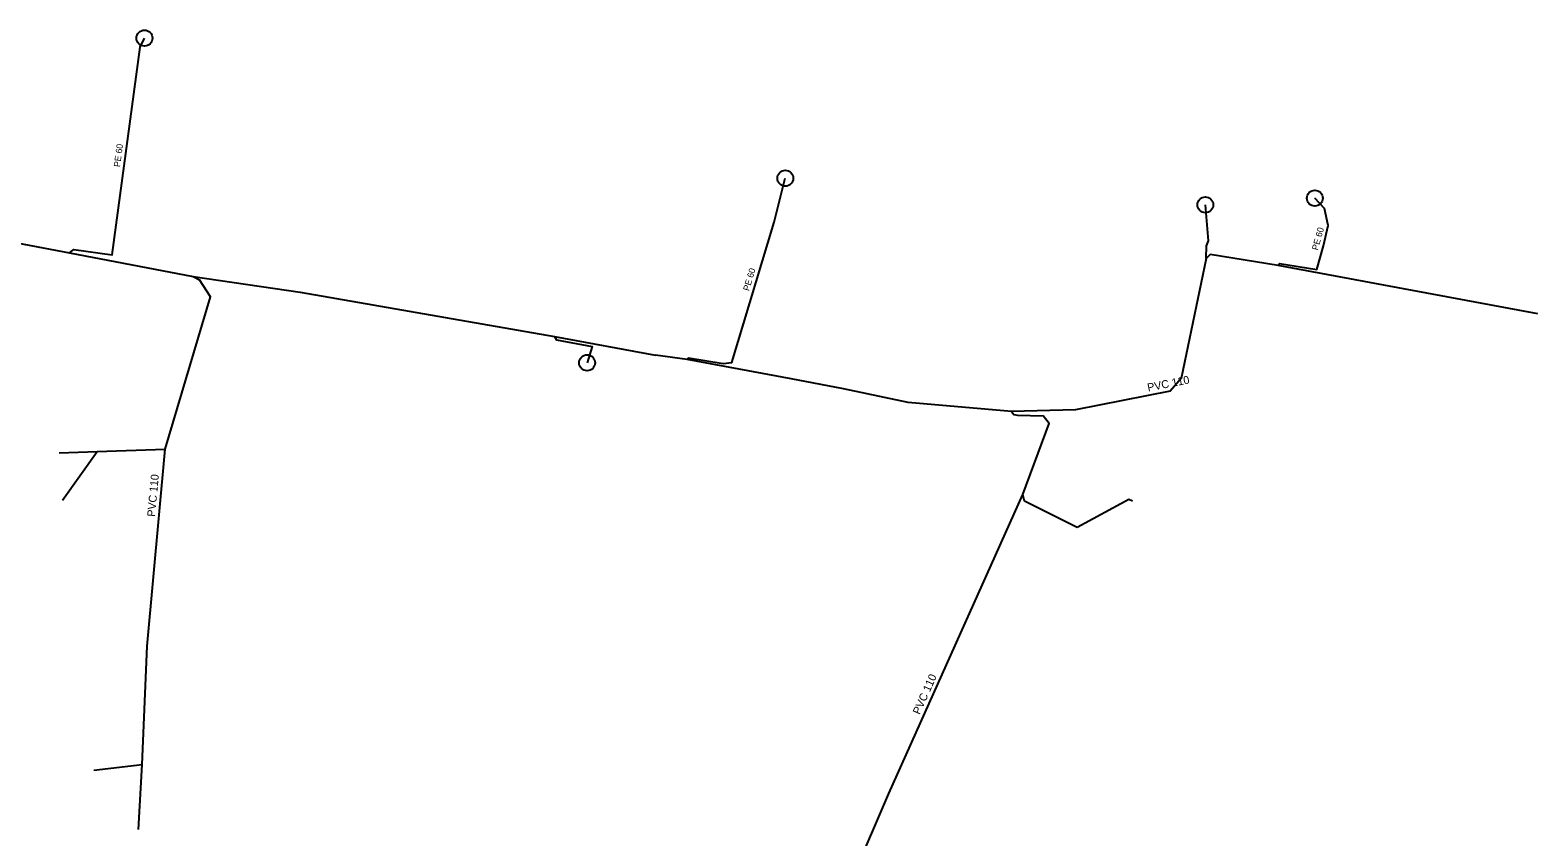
# Model space of a CAD drawing. Extents: x -687195 to -686827, y -1053873 to -1053627.
# Drawn here: x -686921.9 to -686827.2, y -1053773 to -1053722.3 of the extents above; entities that cross this region are included whole.
import ezdxf

# ---------------------------------------------------------------- set-up
doc = ezdxf.new("R2010")
doc.units = 0
for name, color, linetype in [('Kanalizační přípojky', 7, 'Continuous'), ('Kanalizační stoka', 7, 'Continuous'), ('Kanalizační šachty', 7, 'Continuous'), ('Popis', 7, 'Continuous')]:
    doc.layers.add(name, color=color, linetype=linetype)

msp = doc.modelspace()

# ---------------------------------------------------------------- linework, layer by layer
at = {"layer": 'Kanalizační přípojky'}
for points in [[(-686919.46, -1053736.25), (-686919.2, -1053736.04), (-686916.79, -1053736.37), (-686915.02, -1053723.32), (-686914.76, -1053722.75)], [(-686880.65, -1053742.95), (-686880.56, -1053742.85), (-686878.39, -1053743.2), (-686877.84, -1053743.14), (-686875.19, -1053734.31), (-686874.48, -1053731.56)], [(-686848.03, -1053736.6), (-686848.01, -1053735.8), (-686847.89, -1053735.5), (-686848.08, -1053733.23)], [(-686843.5, -1053737.05), (-686843.42, -1053736.92), (-686841.07, -1053737.29), (-686840.66, -1053735.8), (-686840.37, -1053734.52), (-686840.6, -1053733.46), (-686841.2, -1053732.81)], [(-686888.99, -1053741.5), (-686888.87, -1053741.72), (-686886.62, -1053742.13), (-686886.94, -1053743.16)], [(-686920.11, -1053748.81), (-686917.74, -1053748.73)], [(-686919.9, -1053751.8), (-686917.74, -1053748.73)], [(-686917.74, -1053748.73), (-686913.45, -1053748.59)], [(-686856.13, -1053753.52), (-686859.44, -1053751.85), (-686859.56, -1053751.44)], [(-686852.66, -1053751.86), (-686852.89, -1053751.76), (-686856.13, -1053753.52)], [(-686917.95, -1053768.77), (-686914.9, -1053768.41)], [(-686915.14, -1053772.49), (-686914.9, -1053768.41)]]:
    msp.add_lwpolyline(points, dxfattribs=at)
at = {"layer": 'Kanalizační stoka'}
for points in [[(-687011.48, -1053741.84), (-687009.38, -1053742.55), (-687009.16, -1053742.33), (-687007.63, -1053741.25), (-687001.39, -1053736.67), (-686994.3, -1053732.84), (-686988.39, -1053730.31), (-686985.46, -1053729.05), (-686981.83, -1053727.4), (-686971.92, -1053726.39), (-686966.85, -1053726.34), (-686961.83, -1053726.9), (-686959.7, -1053727.22), (-686951.5, -1053728.59), (-686928.1, -1053734.61), (-686919.46, -1053736.25), (-686911.7, -1053737.73), (-686904.97, -1053738.72), (-686888.99, -1053741.5), (-686882.64, -1053742.68)], [(-686827.182, -1053740.076), (-686843.5, -1053737.05), (-686847.77, -1053736.35), (-686848.03, -1053736.6), (-686849.61, -1053744.15), (-686850.29, -1053744.95), (-686856.25, -1053746.12), (-686860.26, -1053746.23), (-686866.76, -1053745.65), (-686870.82, -1053744.8), (-686874.11, -1053744.16), (-686880.65, -1053742.95), (-686882.64, -1053742.68)], [(-686914.9, -1053768.41), (-686914.59, -1053760.98), (-686913.45, -1053748.59), (-686910.6, -1053739.02), (-686911.3, -1053737.95)], [(-686911.7, -1053737.73), (-686911.3, -1053737.95)], [(-686874.05, -1053784.39), (-686870.2, -1053775.42), (-686867.97, -1053770.24), (-686859.56, -1053751.44), (-686857.89, -1053746.98), (-686858.28, -1053746.5)], [(-686860.26, -1053746.23), (-686860.11, -1053746.42), (-686859.89, -1053746.45), (-686858.28, -1053746.5)]]:
    msp.add_lwpolyline(points, dxfattribs=at)
at = {"layer": 'Kanalizační šachty'}
for centre in [(-686914.76, -1053722.75), (-686874.48, -1053731.56), (-686848.08, -1053733.23), (-686841.2, -1053732.81), (-686886.94, -1053743.16)]:
    msp.add_circle(centre, 0.5, dxfattribs=at)

# ---------------------------------------------------------------- texts
at = {"layer": 'Popis'}
for s, height, rotation, p in [('PE 60', 0.4, 82.27598, (-686916.297, -1053730.872)), ('PE 60', 0.4, 74.61481, (-686841.007, -1053736.117)), ('PE 60', 0.4, 73.2948, (-686876.761, -1053738.675)), ('PVC 110', 0.5, 11.10643, (-686851.674, -1053744.967)), ('PVC 110', 0.5, 84.74303, (-686914.094, -1053752.856)), ('PVC 110', 0.5, 65.8991, (-686866.039, -1053765.311))]:
    msp.add_text(s, height=height, rotation=rotation, dxfattribs=at).set_placement(p)

doc.saveas('drawing.dxf')
